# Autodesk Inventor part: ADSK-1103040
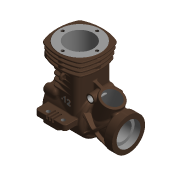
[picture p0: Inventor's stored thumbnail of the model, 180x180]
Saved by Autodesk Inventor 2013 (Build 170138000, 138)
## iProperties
Shininess: 11.0
Compacted: True
Length Units: 11269
Angle Units: 11279
Time Units: 11290
Mass Units: 11286
Length Display Precision: 2
Angle Display Precision: 2
Created: 2000-07
Part Number: ADSK-1103040
Document SubType Name: Modeling
Description: ENGINE  CASE - REAR
Mass: 106.432 g
Surface Area: 158.117 cm^2
Volume: 13.1723 cm^3
Density: 8.08 g/cm^3
Material: Edelstahl
Density: 0.0
Volumn: 0.0
Area: 0.0
PropertySet Name: Model Information
Control State: 0
Master: False
Checked Out: False
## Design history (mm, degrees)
node "Extrusion1" dims "d2" = 3.5, "d3" = 0
workplane "Work Plane1"
workplane "Work Plane2"
node "Extrusion2" dims "d6" = 25.5, "d7" = 0
node "Extrusion3" dims "d13" = 25, "d14" = 0
node "Extrusion5" dims "d18" = 14, "d19" = 0
workplane "Work Plane15"
node "Extrusion6" dims "d21" = 6, "d22" = 0
fillet "Fillet48" dims "d248" = 2
fillet "Fillet53" dims "d264" = 2, "d265" = 1
feature "LoftSrf2" dims "d266" = 0, "d267" = 90 deg, "d268" = 0, "d269" = 90 deg
  node "Edges3"
  node "Edges4"
feature "OffsetSrf1" dims "d270" = 1, "d271" = 1
node "Revolution1" dims "d28" = 90 deg
workplane "Work Plane3"
  workaxis "Work Axis1"
workaxis "Work Axis2"
workplane "Work Plane5"
workplane "Work Plane30"
node "Extrusion12" dims "d54" = 8, "d55" = 0
node "Extrusion13" dims "d56" = 8, "d57" = 0
node "Fillet1" dims "d58" = 2.5
node "Fillet3" dims "d60" = 5
node "Fillet4" dims "d61" = 3
node "Fillet5" dims "d62" = 2
node "Revolution2" dims "d63" = 180 deg
node "Mirror2"
node "Fillet6" dims "d64" = 2.5
node "Fillet8" dims "d66" = 3.5
node "Fillet17" dims "d75" = 2
node "Fillet18" dims "d76" = 0.3
node "Fillet19" dims "d77" = 0.5
node "Extrusion14" dims "d84" = 9, "d85" = 0
node "Extrusion15" dims "d90" = 1, "d91" = 0
node "Fillet26" dims "d92" = 2
workplane "Work Plane6"
node "Extrusion16" dims "d95" = 1, "d96" = 0
workplane "Work Plane7"
node "Extrusion17" dims "d99" = 1, "d100" = 0
workplane "Work Plane8"
node "Extrusion18" dims "d103" = 1, "d104" = 0
node "Extrusion19" dims "d108" = 1, "d109" = 0
workaxis "Work Axis3"
node "Circular Pattern2" dims "d110" = 40, "d112" = 360 deg
node "Fillet27" dims "d113" = 0.3
node "Fillet28" dims "d114" = 0.5
workplane "Work Plane9"
node "Fillet34" dims "d130" = 0.45
feature "Rib1" dims "d246" = 2, "d247" = 1
fillet "Fillet49" dims "d249" = 1
fillet "Fillet50" dims "d250" = 1
fillet "Fillet51" dims "d251" = 1
fillet "Fillet52" dims "d252" = 1
workplane "Work Plane17"
split "Split2"
sketch "Sketch51"
  geometry: L1 (-37.441, 3.747)-(-20.441, -10.747); L2 (-37.441, -10.747)-(-20.441, 3.747); L3 (-37.441, 4.569)-(-37.441, 2.926); L4 (-37.441, 2.926)-(-29.905, -3.5); L5 (-29.905, -3.5)-(-37.441, -9.926); L6 (-37.441, -9.926)-(-37.441, -11.569); L7 (-37.441, -11.569)-(-28.941, -4.321); L8 (-28.941, -4.321)-(-20.441, -11.569); L9 (-20.441, -11.569)-(-20.441, -9.926); L10 (-20.441, -9.926)-(-27.978, -3.5); L11 (-27.978, -3.5)-(-20.441, 2.926); L12 (-20.441, 2.926)-(-20.441, 4.569); L13 (-20.441, 4.569)-(-28.941, -2.679); L14 (-28.941, -2.679)-(-37.441, 4.569); L15 (-37.441, -13.502)-(-37.441, 6.502) reference; L16 (-20.441, -14.502)-(-20.441, 7.502) reference; 2 further points
  constraints: 28 end point, 12 collinear, 8 parallel, 6 midpoint, 2 horizontal alignment, 1 vertical
  dimensions: "d272" = 1.25 distance between parallel lines of L14 L4
extrude "Extrusion38" join sketch "Sketch51" stored distance "d273" = 14; taper "d274" = 0 deg
mirror "Mirror3"
fillet "Fillet54" dims "d275" = 1
fillet "Fillet58" dims "d279" = 10
fillet "Fillet55" dims "d276" = 0.3
fillet "Fillet57" dims "d278" = 0.3
node "Hole1" dims "d139" = 2.013, "d140" = 4, "d141" = 2, "d142" = 60 deg, "d143" = 5, "d144" = 118 deg
node "Extrusion24" dims "d152" = 25, "d153" = 0
node "Extrusion25" dims "d154" = 0.25, "d155" = 0
workaxis "Work Axis8"
workplane "Work Plane33"
node "Fillet38" dims "d156" = 0.5
node "Hole3" dims "d157" = 2.013, "d158" = 4, "d159" = 2, "d160" = 60 deg, "d161" = 8, "d162" = 118 deg
node "Circular Pattern3" dims "d163" = 40, "d165" = 360 deg
workplane "Work Plane10"
node "Extrusion26" dims "d172" = 1, "d173" = 0
node "Fillet39" dims "d174" = 0.3
mirror "Mirror4"
fillet "Fillet59" dims "d281" = 0.5
node "Rectangular Pattern1" dims "d176" = 40, "d178" = 3.5
node "Extrusion27" dims "d180" = 4, "d181" = 0
node "Extrusion28" dims "d183" = 4, "d184" = 0
node "Extrusion29" dims "d186" = 20, "d187" = 0
node "Extrusion30" dims "d189" = 22, "d190" = 0
sketch "Sketch43"
  geometry: L1 (12.324, 33.859)-(-10.939, -30.056); L2 (1.197, 3.289)-(-5.381, 5.683); L3 (-4.342, 9.03)-(5.376, 5.493); L4 (17.596, 48.345)-(-18.614, -51.141) reference; L5 (-8.665, 10.603)-(-8.323, 10.479) reference; L6 (-8.323, 10.479)-(-4.885, 9.227) reference; L7 (-3.975, 8.896)-(-4.885, 9.227) reference; L8 (-3.975, 8.896)-(-3.975, 8.896) reference; L9 (-4.885, 9.227)-(-3.975, 8.896) reference; L10 (-4.885, 9.227)-(-8.323, 10.479) reference; L11 (-8.665, 10.603)-(-8.323, 10.479) reference; C1 r 2.75 at (-5.381, 5.683)
  constraints: 6 end point, 2 collinear, 1 centre point, 1 coincident, 1 perpendicular, 1 point on line
  dimensions: "d216" = 7 distance of L2.start L2.end; "d217" = 3.5 distance between parallel lines of L2 L3; "d218" = 5.5 diameter of C1
extrude "Extrusion39" join sketch "Sketch43" distance "d282" = 14; taper "d283" = 0 deg
fillet "Fillet60" dims "d284" = 0.5
node "Extrusion35" dims "d223" = 15, "d224" = 0
node "Extrusion36" dims "d226" = 15, "d227" = 0
node "Chamfer1" dims "d228" = 0.5, "d229" = 0.5, "d239" = 45 deg
node "Hole4" dims "d233" = 2.5, "d234" = 4, "d235" = 2, "d236" = 60 deg, "d237" = 8, "d238" = 118 deg
sketch "Sketch52"
  geometry: L1 (1.337, 11.656)-(8.684, 11.656); L2 (8.684, 11.656)-(8.684, 8.517); L3 (8.684, 8.517)-(1.337, 8.517); L4 (1.337, 8.517)-(1.337, 11.656)
  constraints: 2 other
emboss "Emboss1" sketch "Sketch52" dims "d288" = 0.333, "d289" = 0
sketch "Sketch53"
  geometry: L1 (-11.887, 5.713)-(-11.887, 13.872); L2 (-11.887, 13.872)-(-8.327, 13.872); L3 (-8.327, 13.872)-(-8.327, 5.713); L4 (-8.327, 5.713)-(-11.887, 5.713)
  constraints: 2 other
emboss "Emboss2" sketch "Sketch53" dims "d293" = 0.33, "d294" = 0
fillet "Fillet77" dims "d396" = 0.25
fillet "Fillet78" dims "d397" = 0.1
fillet "Fillet79" dims "d398" = 0.25
fillet "Fillet80" dims "d399" = 0.1
split "Split4"
split "Split7"
feature "RevolutionSrf1" dims angle "d328" = 10 deg
thicken "Thicken1" dims "d329" = 3, "d330" = 4
node "Extrusion31" dims "d192" = 5, "d193" = 0
fillet "Fillet64" dims "d331" = 0.5
fillet "Fillet65" dims "d332" = 0.5
workplane "Work Plane29"
workplane "Work Plane31"
workaxis "Work Axis7"
sketch "Sketch55"
  geometry: C1 r 6.5 at (0, 23.5); 1 further point
  constraints: 1 centre point, 1 coincident
  dimensions: "d336" = 13 diameter of C1
extrude "Extrusion40" join sketch "Sketch55" stored distance "d337" = 10; taper "d338" = 0 deg
feature "Rib5" dims "d341" = 1, "d342" = 2
fillet "Fillet66" dims "d343" = 0.5
fillet "Fillet67" dims "d394" = 0.4
fillet "Fillet68" dims "d347" = 0.5
sketch "Sketch58"
  geometry: C1 r 6.5 at (0, 0) reference; C2 r 5.25 at (0, 0); C3 r 7.516 at (0, 0); 2 further points
  constraints: 2 centre point, 2 coincident, 1 horizontal alignment
  dimensions: "d348" = 1.25 radial gap between concentric circles of C2 C1
extrude "Extrusion41" cut sketch "Sketch58" distance "d349" = 6 (derived); taper "d350" = 0 deg
hole "Hole5" diameter "d353" = 8; stored, may be unused: countersink angle "d357" = 90 deg, drill point angle "d359" = 118 deg; dims "d351" = 10, "d352" = 10, "d354" = 6, "d355" = 4, "d356" = 2, "d358" = 8
chamfer "Chamfer2" distance "d360" = 0.5; stored, may be unused: second distance "d361" = 2, angle "d362" = 45 deg
fillet "Fillet76" dims "d393" = 0.5
sketch "Sketch59"
  geometry: L1 (12.125, 12.4)-(12.125, 12.5); L2 (15.875, 12.5)-(15.875, 12.4); A1 r 1.875 centre (14, 12.5) between (15.875, 12.5) and (12.125, 12.5); 1 further point
  constraints: 4 end point, 2 parallel, 2 point on circle, 2 tangent, 1 centre point, 1 vertical, 1 vertical alignment
  dimensions: "d364" = 1.875 radius of A1; "d365" = 12.5 distance of point (14, 0) A1.centre; "d366" = 0.1 distance of L1.start L1.end
extrude "Extrusion42" join sketch "Sketch59" distance "d368" = 1.5; taper "d369" = 0 deg
hole "Hole6" diameter "d372" = 1.5; stored, may be unused: countersink angle "d376" = 90 deg, drill point angle "d378" = 118 deg; dims "d370" = 10, "d371" = 10, "d373" = 6, "d374" = 4, "d375" = 2, "d377" = 8
fillet "Fillet69" dims "d379" = 0.5
mirror "Mirror5"
fillet "Fillet70" dims "d380" = 0.5
fillet "Fillet71" dims "d381" = 0.3
workplane "Work Plane34"
revolve "Revolution3" stored, may be unused: angle "d384" = 45 deg
fillet "Fillet72" dims "d385" = 2
fillet "Fillet73" dims "d386" = 1
mirror "Mirror6"
fillet "Fillet74" dims "d387" = 2
fillet "Fillet75" dims "d388" = 1
sketch "Sketch61" dims "d405" = 10
  geometry: L1 (3.2, 16)-(3.2, 0) reference; L2 (3.5, 10.482)-(1.5, 10.482); L3 (1.5, 10.482)-(1.5, 9.482); L4 (1.5, 9.482)-(3.5, 9.482); L5 (3.5, 9.482)-(3.5, 10.482); L6 (3.5, 8.482)-(1.5, 8.482); L7 (1.5, 8.482)-(1.5, 7.482); L8 (1.5, 7.482)-(3.5, 7.482); L9 (3.5, 7.482)-(3.5, 8.482); L10 (3.5, 6.482)-(1.5, 6.482); L11 (1.5, 6.482)-(1.5, 5.482); L12 (1.5, 5.482)-(3.5, 5.482); L13 (3.5, 5.482)-(3.5, 6.482); L14 (47.7, 7.982)-(-21.95, 7.982) reference; L15 (3.5, 0)-(3.5, 16) reference
  constraints: 24 end point, 6 parallel, 3 perpendicular, 1 collinear, 1 horizontal, 1 vertical, 17 other
  dimensions: "d402" = 2 distance of L2.start L6.start; "d407" = 1 distance of L4.end L2.start; "d408" = 2 distance of L2.start L2.end
extrude "Extrusion43" cut sketch "Sketch61" distance "d409" = 6; taper "d410" = 0 deg
fillet "Fillet81" dims "d411" = 0.5
mirror "Mirror7"
revolve "Revolution4" stored, may be unused: angle "d425" = 90 deg
workplane "Work Plane35"
node "Volumenkörper1"
node "Volumenkörper"
node "Oberflächenkörper"
sketch "Sketch2"
  geometry: L1 (-28.715, -16.977)-(11.285, -16.977); L2 (11.285, -16.977)-(11.285, 3.023); L3 (11.285, 3.023)-(-28.715, 3.023); L4 (-28.715, 3.023)-(-28.715, -16.977)
  constraints: 8 end point, 2 parallel, 1 horizontal, 1 perpendicular
  dimensions: "d0" = 40 distance of L2.end L3.end; "d1" = 20 distance of L3.end L1.start
sketch "Sketch3"
  geometry: L1 (20, -16.8)-(20, 16.8) reference; L2 (0, 0)-(40, 0) reference; C1 r 12 at (20, 0)
  constraints: 1 centre point, 1 midpoint
  dimensions: "d5" = 24 diameter of C1
sketch "Sketch4"
  geometry: L1 (-20.715, 3.023)-(3.285, 3.023); L2 (-2.715, -16.977)-(-14.715, -16.977); L3 (-8.715, -21.506)-(-8.715, 7.111) reference; L4 (-28.715, -16.977)-(-20.715, -16.977) reference; A1 r 36.333 centre (-33.049, 3.023) between (-2.715, -16.977) and (3.285, 3.023); A2 r 36.333 centre (15.618, 3.023) between (-20.715, 3.023) and (-14.715, -16.977)
  constraints: 4 end point, 4 point on circle, 2 centre point, 2 point on line, 1 collinear, 1 horizontal
  dimensions: "d8" = 24 distance of L1.start L1.end; "d9" = 12 distance of L2.start L2.end; "d10" = 6 distance from line of L3 L2.start (= 0.5 x d9); "d11" = 12 distance from line of L1.end L3 (= 0.5 x d8); "d12" = 20 distance between parallel lines of L2 L1
sketch "Sketch6"
  geometry: C1 r 11.33 at (0, 0); C2 r 8 at (0, 0); C3 r 12 at (0, 0) reference
  constraints: 2 centre point, 1 coincident
  dimensions: "d17" = 16 diameter of C2
sketch "Sketch7"
  geometry: C1 r 7.5 at (0, 0); C2 r 11 at (0, 0)
  constraints: 2 centre point, 1 coincident
  dimensions: "d20" = 22 diameter of C2
sketch "Sketch10"
  geometry: L1 (-20, -3.5)-(0, -3.5) reference; L2 (-20.351, 1.344)-(-25.14, 14.5); L3 (-25.14, 14.5)-(-31.718, 12.106); L4 (-31.718, 12.106)-(-26.929, -1.05); L5 (-26.929, -1.05)-(-20.351, 1.344); L6 (-22.5, 4.5)-(-36.5, 4.5) reference; L7 (-22.5, -15.5)-(-22.5, 8.5) reference; 1 further point
  constraints: 8 end point, 2 perpendicular, 2 point on line, 1 parallel
  dimensions: "d26" = 70 deg angle of L1 L2; "d27" = 14 diameter of L2 L4; "d231" = 14 distance of L2.start L2.end; "d241" = 10 distance from line of L6 L2.end; "d242" = 1 distance from line of L7 point (-21.5, 4.5)
sketch "Sketch15"
  geometry: L1 (-9, 9)-(9, 9); L2 (9, 9)-(9, -9); L3 (9, -9)-(-9, -9); L4 (-9, -9)-(-9, 9); C1 r 12 at (0, 0) reference; C2 r 2.5 at (-9, 9); C3 r 2.5 at (9, 9); C4 r 2.5 at (9, -9); C5 r 2.5 at (-9, -9)
  constraints: 8 end point, 4 centre point, 4 coincident, 3 equal radius, 2 parallel, 2 perpendicular, 1 horizontal
  dimensions: "d50" = 18 distance of L2.end L3.end; "d51" = 9 distance from line of C1.centre L4 (= 0.5 x d50); "d52" = 9 distance from line of C1.centre L3 (= d51); "d53" = 5 diameter of C3
sketch "Sketch16"
  geometry: L1 (10.857, -11.496)-(19.314, -11.98); L2 (29.143, -11.496)-(20.686, -11.98); A1 r 2.5 centre (11, -9) between (10.039, -6.692) and (13.308, -9.961) reference; A2 r 12 centre (20, 0) between (13.308, -9.961) and (26.692, -9.961) reference; A3 r 2.5 centre (29, -9) between (26.692, -9.961) and (29.961, -6.692) reference
  constraints: 4 end point, 4 point on circle, 4 tangent
sketch "Sketch17"
  geometry: L1 (0.686, 11.98)-(9.143, 11.496) reference; L2 (9.143, 11.496)-(0.686, 11.98); L3 (0.686, 11.98)-(0.543, 9.484); L4 (0.543, 9.484)-(9, 9); L5 (9, 9)-(9.143, 11.496); L6 (9, 9)-(11.496, 8.857); A1 r 12 centre (0, 0) between (9.961, 6.692) and (0.686, 11.98) reference; A2 r 2.5 centre (9, 9) between (9.961, 6.692) and (9.143, 11.496) reference
  constraints: 10 end point, 3 equal length, 2 perpendicular, 2 tangent, 1 point on circle, 1 point on line
sketch "Sketch18"
  geometry: L1 (-17.028, 3.023)-(-0.402, 3.023) reference; L2 (-8.715, -25.077)-(-8.715, 10.623) reference; C1 r 10.018 at (-8.715, -6.996); A1 r 36.333 centre (15.618, 3.023) between (-20.508, -0.85) and (-16.281, -14.371) reference
  constraints: 2 tangent, 1 centre point, 1 point on line
sketch "Sketch19"
  geometry: L1 (5.035, 6.754)-(-22.465, 6.754); L2 (-22.465, 6.754)-(-22.465, -20.746); L3 (-22.465, -20.746)-(5.035, -20.746); L4 (5.035, -20.746)-(5.035, 6.754); A1 r 10.018 centre (-8.715, -6.996) between (0.549, -10.81) and (-8.715, 3.023) reference; A2 r 27.5 centre (-22.465, -6.996) between (2.599, -18.31) and (2.599, 4.319); A3 r 27.5 centre (5.035, -6.996) between (-20.03, 4.319) and (-20.03, -18.31); A4 r 27.5 centre (-8.715, 6.754) between (-20.03, -18.31) and (2.599, -18.31); A5 r 27.5 centre (-8.715, -20.746) between (2.599, 4.319) and (-20.03, 4.319); A6 r 29.032 centre (-8.715, -20.746) between (-22.465, 4.823) and (-23.458, 4.264)
  constraints: 12 point on circle, 8 end point, 5 centre point, 3 midpoint, 3 tangent, 2 parallel, 2 perpendicular, 1 horizontal, 1 point on line
  dimensions: "d86" = 27.5 distance of L2.end L3.end; "d87" = 13.75 distance from line of L4 A1.centre (= 0.5 x d86); "d88" = 13.75 distance from line of L3 A1.centre (= d87); "d89" = 13.75 distance from line of L2 A4.centre (= d87)
sketch "Sketch20"
  geometry: A1 r 27.5 centre (-8.715, -20.746) between (1.847, 4.645) and (-19.278, 4.645) reference; A2 r 27.5 centre (5.035, -6.996) between (-20.356, 3.567) and (-20.356, -17.558) reference; A3 r 2 centre (-18.509, 2.798) between (-19.278, 4.645) and (-20.356, 3.567) reference; A4 r 2 centre (1.079, 2.798) between (2.925, 3.567) and (1.847, 4.645) reference; A5 r 27.5 centre (-22.465, -6.996) between (2.925, -17.558) and (2.925, 3.567) reference; A6 r 2 centre (1.079, -16.79) between (1.847, -18.636) and (2.925, -17.558) reference; A7 r 27.5 centre (-8.715, 6.754) between (-19.278, -18.636) and (1.847, -18.636) reference; A8 r 2 centre (-18.509, -16.79) between (-20.356, -17.558) and (-19.278, -18.636) reference; A9 r 28 centre (-8.715, -20.746) between (2.039, 5.107) and (-19.47, 5.107); A10 r 2.5 centre (1.079, 2.798) between (3.387, 3.759) and (2.039, 5.107); A11 r 28 centre (-22.465, -6.996) between (3.387, -17.75) and (3.387, 3.759); A12 r 2.5 centre (1.079, -16.79) between (2.039, -19.098) and (3.387, -17.75); A13 r 28 centre (-8.715, 6.754) between (-19.47, -19.098) and (2.039, -19.098); A14 r 2.5 centre (-18.509, -16.79) between (-20.818, -17.75) and (-19.47, -19.098); A15 r 28 centre (5.035, -6.996) between (-20.818, 3.759) and (-20.818, -17.75); A16 r 2.5 centre (-18.509, 2.798) between (-19.47, 5.107) and (-20.818, 3.759)
  constraints: 16 point on circle, 8 centre point, 7 other
  dimensions: "d94" = 0.5 radial gap between concentric circles of A9 A1
sketch "Sketch21"
  geometry: A1 r 28 centre (-8.715, -20.746) between (2.039, 5.107) and (-19.47, 5.107) reference; A2 r 28 centre (5.035, -6.996) between (-20.818, 3.759) and (-20.818, -17.75) reference; A3 r 2.5 centre (-18.509, -16.79) between (-20.818, -17.75) and (-19.47, -19.098) reference; A4 r 2.5 centre (-18.509, 2.798) between (-19.47, 5.107) and (-20.818, 3.759) reference; A5 r 28 centre (-8.715, 6.754) between (-19.47, -19.098) and (2.039, -19.098) reference; A6 r 2.5 centre (1.079, -16.79) between (2.039, -19.098) and (3.387, -17.75) reference; A7 r 28 centre (-22.465, -6.996) between (3.387, -17.75) and (3.387, 3.759) reference; A8 r 2.5 centre (1.079, 2.798) between (3.387, 3.759) and (2.039, 5.107) reference; A9 r 28.5 centre (-8.715, -20.746) between (2.231, 5.568) and (-19.662, 5.568); A10 r 3 centre (1.079, 2.798) between (3.849, 3.951) and (2.231, 5.568); A11 r 28.5 centre (-22.465, -6.996) between (3.849, -17.942) and (3.849, 3.951); A12 r 3 centre (1.079, -16.79) between (2.231, -19.56) and (3.849, -17.942); A13 r 28.5 centre (-8.715, 6.754) between (-19.662, -19.56) and (2.231, -19.56); A14 r 3 centre (-18.509, -16.79) between (-21.279, -17.942) and (-19.662, -19.56); A15 r 28.5 centre (5.035, -6.996) between (-21.279, 3.951) and (-21.279, -17.942); A16 r 3 centre (-18.509, 2.798) between (-19.662, 5.568) and (-21.279, 3.951)
  constraints: 16 point on circle, 8 centre point, 7 other
  dimensions: "d98" = 0.5 radial gap between concentric circles of A9 A1
sketch "Sketch22"
  geometry: A1 r 28.5 centre (-8.715, -20.746) between (2.231, 5.568) and (-19.662, 5.568) reference; A2 r 3 centre (-18.509, 2.798) between (-19.662, 5.568) and (-21.279, 3.951) reference; A3 r 28.5 centre (5.035, -6.996) between (-21.279, 3.951) and (-21.279, -17.942) reference; A4 r 3 centre (-18.509, -16.79) between (-21.279, -17.942) and (-19.662, -19.56) reference; A5 r 28.5 centre (-8.715, 6.754) between (-19.662, -19.56) and (2.231, -19.56) reference; A6 r 3 centre (1.079, -16.79) between (2.231, -19.56) and (3.849, -17.942) reference; A7 r 28.5 centre (-22.465, -6.996) between (3.849, -17.942) and (3.849, 3.951) reference; A8 r 3 centre (1.079, 2.798) between (3.849, 3.951) and (2.231, 5.568) reference; A9 r 29 centre (-8.715, -20.746) between (2.423, 6.03) and (-19.854, 6.03); A10 r 3.5 centre (1.079, 2.798) between (4.31, 4.143) and (2.423, 6.03); A11 r 29 centre (-22.465, -6.996) between (4.31, -18.134) and (4.31, 4.143); A12 r 3.5 centre (1.079, -16.79) between (2.423, -20.021) and (4.31, -18.134); A13 r 29 centre (-8.715, 6.754) between (-19.854, -20.021) and (2.423, -20.021); A14 r 3.5 centre (-18.509, -16.79) between (-21.741, -18.134) and (-19.854, -20.021); A15 r 29 centre (5.035, -6.996) between (-21.741, 4.143) and (-21.741, -18.134); A16 r 3.5 centre (-18.509, 2.798) between (-19.854, 6.03) and (-21.741, 4.143)
  constraints: 16 point on circle, 8 centre point, 7 other
  dimensions: "d102" = 0.5 radial gap between concentric circles of A9 A1
sketch "Sketch23" dims "d105" = 23
  geometry: L1 (-8.715, -31.799)-(-8.715, 35.076) reference; C1 r 10.018 at (-8.715, -6.996) reference; A1 r 2 centre (-8.715, 4.504) between (-6.717, 4.422) and (-10.714, 4.422); A2 r 2 centre (-4.719, 4.339) between (-6.717, 4.422) and (-5.384, 2.453); A3 r 2 centre (-12.712, 4.339) between (-12.047, 2.453) and (-10.714, 4.422); A4 r 10.018 centre (-8.715, -6.996) between (-5.384, 2.453) and (-12.047, 2.453); 1 further point
  constraints: 8 point on circle, 4 centre point, 4 tangent, 2 equal radius, 1 coincident, 1 concentric, 1 point on line, 1 vertical alignment, 2 other
  dimensions: "d106" = 4 diameter of A1; "d107" = 2 radius of A2
sketch "Sketch28"
  geometry: A1 r 2.5 centre (29, 9) between (30.967, 7.457) and (27.457, 10.967) reference; A2 r 2.5 centre (11, 9) between (12.543, 10.967) and (9.033, 7.457) reference; A3 r 2.5 centre (11, -9) between (8.939, -7.585) and (10.857, -11.496) reference; A4 r 2.5 centre (29, -9) between (29.143, -11.496) and (31.061, -7.585) reference
sketch "Sketch30"
  geometry: C1 r 9 at (-8.715, -6.996); A1 r 10.518 centre (-8.715, -6.996) between (-18.635, -10.493) and (-12.213, -16.915) reference
  constraints: 1 centre point, 1 coincident
  dimensions: "d151" = 18 diameter of C1
sketch "Sketch31"
  geometry: C1 r 9 at (-8.715, -6.996) reference; A1 r 28.7 centre (-8.715, 6.754) between (-19.739, -19.744) and (2.308, -19.744) reference; 1 further point
  constraints: 1 coincident, 1 vertical alignment, 2 other
sketch "Sketch32"
  geometry: A1 r 2.5 centre (-8.715, 4.504) between (-6.218, 4.401) and (-11.213, 4.401) reference; 2 further points
sketch "Sketch33"
  geometry: L1 (20.526, -0.599)-(20.124, -12.117); L2 (18.879, -14.443)-(13.845, -16.58); L3 (15.656, -15.268)-(18.907, -13.888); L4 (0.402, 3.023)-(17.028, 3.023) reference; A1 r 36.333 centre (-15.618, 3.023) between (16.281, -14.371) and (20.508, -0.85) reference; A2 r 3.5 centre (17.028, -0.477) between (20.508, -0.85) and (17.028, 3.023) reference; A3 r 5 centre (11.892, -11.977) between (11.892, -16.977) and (16.281, -14.371) reference; A4 r 2 centre (18.125, -12.047) between (18.907, -13.888) and (20.124, -12.117)
  constraints: 6 end point, 5 point on circle, 4 tangent, 1 centre point, 1 parallel
  dimensions: "d168" = 115 deg angle of L2 L1; "d170" = 2 radius of A4; "d171" = 0.5 distance between parallel lines of L2 L3; "d280" = 88 deg angle of L4 L1
sketch "Sketch34"
  geometry: C1 r 11 at (0, 0); C2 r 8 at (0, 0); A1 r 11 centre (0, 0) between (-11, 0) and (11, 0) reference; A2 r 11 centre (0, 0) between (11, 0) and (-11, 0) reference
  constraints: 2 centre point, 1 coincident
  dimensions: "d179" = 16 diameter of C2
sketch "Sketch35"
  geometry: C1 r 8 at (0, 0) reference; C2 r 6 at (0, 0)
  constraints: 1 centre point, 1 coincident
  dimensions: "d182" = 12 diameter of C2
sketch "Sketch36"
  geometry: C1 r 10.5 at (20, 0); A1 r 12 centre (20, 0) between (30.859, -5.106) and (30.749, 5.334) reference
  constraints: 1 centre point, 1 coincident
  dimensions: "d185" = 21 diameter of C1
sketch "Sketch37"
  geometry: C1 r 7 at (-8.715, -6.996); A1 r 13.75 centre (-8.715, -6.996) between (5.035, -6.996) and (-22.465, -6.996) reference
  constraints: 1 centre point, 1 coincident
  dimensions: "d188" = 14 diameter of C1
sketch "Sketch38"
  geometry: C1 r 10.5 at (0, 0) reference; C2 r 9.5 at (0, 0)
  constraints: 1 centre point, 1 coincident
  dimensions: "d191" = 19 diameter of C2
sketch "Sketch44"
  geometry: C1 r 5.5 at (0, 0); A1 r 7 centre (0, 0) between (1.75, -6.778) and (-1.75, -6.778) reference
  constraints: 1 centre point, 1 concentric
  dimensions: "d222" = 11 diameter of C1
sketch "Sketch45"
  geometry: C1 r 2.75 at (0, 0); C2 r 2 at (0, 0); C3 r 2.75 at (0, 0) reference
  constraints: 2 centre point, 1 coincident
  dimensions: "d225" = 4 diameter of C2
sketch "Sketch46"
  geometry: C1 r 1.078 at (8.285, -11.027) reference; C2 r 1.078 at (8.285, -1.027) reference; C3 r 1.078 at (-25.715, -1.977) reference; C4 r 1.078 at (-25.715, -11.977) reference
sketch "Sketch47"
  geometry: L1 (0, 8.296)-(0, -10.725)
  constraints: 2 end point, 1 vertical
node "Fläche1"
node "Fläche2"
node "Projected Loop1"
sketch "Sketch54"
  geometry: L1 (-37.441, -13.502)-(-20.441, -14.502) reference; L2 (-34.186, -13.693)-(-24.164, -14.283); L3 (11.1, -3.5)-(-45.6, -3.5) reference; A1 r 1 centre (-37.5, -13.5) between (-37.5, -14.5) and (-36.5, -13.5) reference; A2 r 2 centre (-20.5, -13.5) between (-22.5, -13.5) and (-20.5, -15.5) reference; A3 r 1 centre (-37.5, -13.5) between (-37.5, -14.5) and (-36.997, -14.364); A4 r 2 centre (-20.5, -13.5) between (-21.631, -15.15) and (-20.5, -15.5); A5 r 5 centre (-34.48, -18.685) between (-34.186, -13.693) and (-36.997, -14.364); A6 r 5 centre (-24.457, -19.274) between (-21.631, -15.15) and (-24.164, -14.283)
  constraints: 10 point on circle, 5 tangent, 4 centre point, 3 equal radius, 2 end point, 1 collinear, 1 point on line
  dimensions: "d295" = 5 radius of A5
node "Fläche3"
sketch "Sketch57"
  geometry: L1 (2.25, 9.25)-(2.25, 8.75); L2 (3, 1.834)-(3, -8.606) reference; L3 (3, 8.5)-(2, 8.5) reference
  constraints: 2 end point, 1 vertical
  dimensions: "d389" = 0.75 distance between parallel lines of L2 L1; "d390" = 0.25 distance from line of L3 L1.end; "d391" = 0.5 distance of L1.start L1.end
sketch "Sketch60"
  geometry: L1 (11.964, 9.428)-(11.964, 10.362); L2 (11.964, 10.362)-(29.739, 10.362); L3 (-10.2, 0)-(59.45, 0) reference
  constraints: 4 end point, 1 parallel, 1 perpendicular, 1 vertical
sketch "Sketch62"
  geometry: L1 (8.5, 25.25)-(3, 25.25) reference; L2 (3, 23.411)-(3, 13.5) reference; L3 (5, 25.25)-(6.5, 25.25); L4 (6.5, 25.25)-(6.5, 24.5); L5 (6.5, 24.5)-(5, 24.5); L6 (5, 24.5)-(5, 25.25); L7 (9, 24.75)-(9, 15.25) reference; L8 (9, 20)-(8.345, 20)
  constraints: 10 end point, 2 parallel, 2 perpendicular, 1 horizontal, 1 midpoint, 1 point on line
  dimensions: "d422" = 0.75 distance of L3.end L4.end; "d423" = 1.5 distance between parallel lines of L4 L6; "d424" = 2.5 distance between parallel lines of L7 L4
other parameters: "d4" = 3, "d37" = 45 deg, "d93" = 2, "d97" = 2, "d101" = 2, "d115" = -15, "d166" = 2, "d240" = 14, "d259" = 0, "d333" = 9, "d334" = 0, "d335" = 23.5, "d345" = 0, "d367" = 1.5, "d383" = 30 deg, "d418" = 40 deg
